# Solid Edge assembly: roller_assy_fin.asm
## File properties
Author: mokuno
Template: Sync Jis Assembly.asm
Last saved by: mokuno
Revision: 4
Application: Solid Edge
文書内容のタイプ: 1
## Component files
baseplate1.par
support1.par
roller1.par
bolt24x50.par
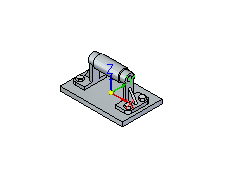
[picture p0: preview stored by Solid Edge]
